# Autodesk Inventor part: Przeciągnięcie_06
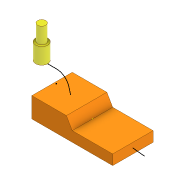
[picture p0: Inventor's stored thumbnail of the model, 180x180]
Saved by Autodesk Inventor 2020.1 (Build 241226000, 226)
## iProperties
Manager: www.cadconsulting.pl
Company: Fabian Stasiak CAD Consulting
Created: 2019-07
Part Number: Przeciągnięcie_06
Material: Ogólny
Document SubType Name: Modeling
Designer: F.Stasiak
Density: 1 g/cm^3
Appearance: Pomarańczowa
Author: F.Stasiak
Subject: Zbiór ćwiczeń. Autodesk Inventor 2020. Kurs podstawowy
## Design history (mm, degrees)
sketch "Szkic1"
  geometry: L1 (-100, 25)-(100, 25); L2 (100, 25)-(100, -25); L3 (100, -25)-(-100, -25); L4 (-100, -25)-(-100, 25); L5 (-100, 25)-(100, -25); L6 (100, 25)-(-100, -25); 1 further point
  constraints: 12 end point, 2 midpoint, 2 parallel, 1 horizontal, 1 perpendicular
  dimensions: "d0" = 200 distance of L2.end L3.end; "d1" = 50 distance of L1.end L2.end
extrude "Wyciągnięcie proste1" new body sketch "Szkic1" stored distance "d2" = 100; taper "d3" = 0 deg
sketch "Szkic2"
  geometry: L1 (-125.651, 62.949)-(-89.467, 62.949); L2 (-58.786, 39.833)-(-52.042, 16.323); L3 (-36.007, 2.805)-(128.368, -15.264); A1 r 31.919 centre (-89.467, 31.031) between (-58.786, 39.833) and (-89.467, 62.949); A2 r 18.821 centre (-33.951, 21.513) between (-52.042, 16.323) and (-36.007, 2.805); 1 further point
  constraints: 6 end point, 4 point on circle, 4 tangent, 2 centre point, 1 horizontal
node "Płaszczyzna konstrukcyjna1"
sketch "Szkic3"
  geometry: L1 (0, 12.422)-(0, -12.422); 3 further points
  constraints: 2 end point, 1 coincident, 1 midpoint, 1 vertical
node "Płaszczyzna konstrukcyjna2"
sketch "Szkic4"
  geometry: C1 r 15 at (0, 0); 2 further points
  constraints: 1 centre point, 1 coincident
  dimensions: "d5" = 30 diameter of C1
extrude "Wyciągnięcie proste2" new body sketch "Szkic4" distance "d6" = 40; taper "d7" = 0 deg
sketch "Szkic5"
  geometry: C1 r 15 at (0, 0) reference; C2 r 10 at (0, 0); 1 further point
  constraints: 1 centre point, 1 coincident
  dimensions: "d8" = 20 diameter of C2
extrude "Wyciągnięcie proste3" join sketch "Szkic5" distance "d9" = 40; taper "d10" = 0 deg
sketch "Szkic6"
  geometry: L1 (100, 25)-(-100, 25) reference; L2 (100, -25)-(100, 25) reference; L3 (100, 0)-(0, 0); L4 (0, 0)-(-14.434, 25)
  constraints: 4 end point, 1 horizontal, 1 midpoint, 1 point on line
  dimensions: "d13" = 120 deg angle of L4 L3
extrude "Wyciągnięcie proste4" cut sketch "Szkic6" extent not by distance; stored distance "d14" = 0; taper "d15" = 0 deg
node "Bryła1"
node "Bryła2"
other parameters: "d4" = 90 deg
